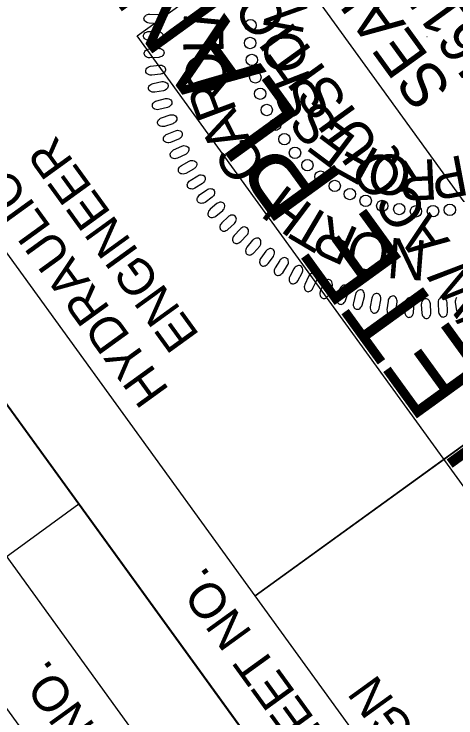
# Model space of a CAD drawing. Extents: x 474248 to 476123, y 501895 to 503900.
# Drawn here: x 474331.8 to 474393.9, y 503181.5 to 503280.5 of the extents above; entities that cross this region are included whole.
import ezdxf

# ---------------------------------------------------------------- set-up
doc = ezdxf.new("R2010")
doc.units = 0
for name, color, linetype in [('Sheet PE Seal Cell', 7, 'Continuous'), ('Sheet Plan CELL', 7, 'Continuous'), ('Sheet Sticker Incomplete CELL', 7, 'Continuous')]:
    doc.layers.add(name, color=color, linetype=linetype)

msp = doc.modelspace()

# ---------------------------------------------------------------- linework, layer by layer
at = {"layer": 'Sheet PE Seal Cell'}
msp.add_line((474389.783, 503277.324), (474389.821, 503277.351), dxfattribs=at)
for points in [[(474351.998, 503279.136), (474350.774, 503279.215), (474350.558, 503279.266), (474350.422, 503279.328), (474350.259, 503279.451), (474350.156, 503279.555), (474350.084, 503279.672), (474350.051, 503279.778), (474350.039, 503279.892), (474350.065, 503280.002), (474350.103, 503280.12), (474350.17, 503280.221), (474350.276, 503280.318), (474350.359, 503280.373), (474350.513, 503280.43), (474350.696, 503280.479), (474350.857, 503280.491), (474352.111, 503280.417), (474352.279, 503280.383), (474352.416, 503280.329), (474352.569, 503280.23), (474352.701, 503280.109), (474352.775, 503280.007), (474352.824, 503279.846), (474352.834, 503279.695), (474352.785, 503279.549), (474352.728, 503279.448), (474352.62, 503279.328), (474352.444, 503279.22), (474352.259, 503279.164), (474352.128, 503279.142)], [(474351.962, 503276.771), (474350.736, 503276.773), (474350.516, 503276.811), (474350.376, 503276.863), (474350.207, 503276.976), (474350.098, 503277.073), (474350.018, 503277.185), (474349.978, 503277.291), (474349.958, 503277.403), (474349.978, 503277.514), (474350.009, 503277.634), (474350.069, 503277.738), (474350.169, 503277.843), (474350.249, 503277.903), (474350.398, 503277.97), (474350.578, 503278.029), (474350.738, 503278.051), (474351.994, 503278.056), (474352.164, 503278.033), (474352.304, 503277.988), (474352.463, 503277.898), (474352.603, 503277.786), (474352.682, 503277.688), (474352.741, 503277.531), (474352.761, 503277.382), (474352.721, 503277.232), (474352.671, 503277.128), (474352.571, 503277.001), (474352.401, 503276.882), (474352.221, 503276.815), (474352.091, 503276.785)], [(474352.103, 503274.404), (474350.879, 503274.33), (474350.658, 503274.353), (474350.516, 503274.397), (474350.339, 503274.499), (474350.223, 503274.589), (474350.137, 503274.696), (474350.091, 503274.798), (474350.065, 503274.909), (474350.077, 503275.022), (474350.101, 503275.143), (474350.153, 503275.251), (474350.247, 503275.362), (474350.323, 503275.426), (474350.468, 503275.503), (474350.644, 503275.573), (474350.801, 503275.605), (474352.055, 503275.689), (474352.226, 503275.677), (474352.368, 503275.641), (474352.533, 503275.561), (474352.679, 503275.458), (474352.765, 503275.366), (474352.834, 503275.212), (474352.863, 503275.064), (474352.832, 503274.913), (474352.788, 503274.805), (474352.697, 503274.672), (474352.535, 503274.543), (474352.36, 503274.465), (474352.232, 503274.427)], [(474352.35, 503272.042), (474351.133, 503271.891), (474350.911, 503271.901), (474350.766, 503271.935), (474350.584, 503272.026), (474350.463, 503272.109), (474350.37, 503272.21), (474350.317, 503272.309), (474350.284, 503272.418), (474350.29, 503272.532), (474350.305, 503272.654), (474350.351, 503272.765), (474350.437, 503272.881), (474350.509, 503272.951), (474350.649, 503273.036), (474350.82, 503273.117), (474350.975, 503273.16), (474352.222, 503273.322), (474352.393, 503273.32), (474352.537, 503273.293), (474352.706, 503273.224), (474352.859, 503273.13), (474352.95, 503273.043), (474353.029, 503272.895), (474353.067, 503272.749), (474353.046, 503272.595), (474353.009, 503272.485), (474352.926, 503272.347), (474352.772, 503272.207), (474352.603, 503272.119), (474352.477, 503272.073)], [(474352.774, 503269.726), (474351.568, 503269.499), (474351.346, 503269.495), (474351.199, 503269.52), (474351.011, 503269.599), (474350.886, 503269.674), (474350.787, 503269.77), (474350.728, 503269.865), (474350.687, 503269.972), (474350.687, 503270.085), (474350.693, 503270.209), (474350.733, 503270.323), (474350.812, 503270.444), (474350.879, 503270.517), (474351.014, 503270.611), (474351.179, 503270.703), (474351.331, 503270.755), (474352.565, 503270.995), (474352.735, 503271.005), (474352.881, 503270.986), (474353.055, 503270.928), (474353.213, 503270.844), (474353.309, 503270.763), (474353.397, 503270.62), (474353.444, 503270.476), (474353.433, 503270.323), (474353.403, 503270.211), (474353.329, 503270.067), (474353.184, 503269.918), (474353.02, 503269.818), (474352.899, 503269.766)], [(474353.332, 503267.363), (474352.143, 503267.06), (474351.921, 503267.043), (474351.773, 503267.058), (474351.581, 503267.126), (474351.45, 503267.193), (474351.345, 503267.282), (474351.281, 503267.373), (474351.234, 503267.477), (474351.226, 503267.59), (474351.225, 503267.714), (474351.258, 503267.83), (474351.328, 503267.956), (474351.391, 503268.034), (474351.519, 503268.136), (474351.678, 503268.238), (474351.827, 503268.299), (474353.043, 503268.617), (474353.213, 503268.636), (474353.36, 503268.628), (474353.536, 503268.58), (474353.699, 503268.506), (474353.801, 503268.432), (474353.897, 503268.294), (474353.953, 503268.154), (474353.951, 503267.999), (474353.929, 503267.885), (474353.864, 503267.738), (474353.729, 503267.58), (474353.572, 503267.47), (474353.453, 503267.41)], [(474354.075, 503265.083), (474352.908, 503264.706), (474352.687, 503264.674), (474352.539, 503264.681), (474352.343, 503264.736), (474352.209, 503264.795), (474352.098, 503264.876), (474352.028, 503264.964), (474351.975, 503265.065), (474351.959, 503265.177), (474351.951, 503265.301), (474351.976, 503265.419), (474352.039, 503265.548), (474352.096, 503265.63), (474352.218, 503265.74), (474352.37, 503265.852), (474352.515, 503265.923), (474353.709, 503266.315), (474353.877, 503266.347), (474354.024, 503266.346), (474354.203, 503266.31), (474354.371, 503266.246), (474354.476, 503266.178), (474354.582, 503266.047), (474354.646, 503265.91), (474354.654, 503265.756), (474354.639, 503265.642), (474354.583, 503265.49), (474354.459, 503265.324), (474354.308, 503265.205), (474354.194, 503265.137)], [(474354.891, 503262.895), (474353.75, 503262.446), (474353.532, 503262.401), (474353.382, 503262.398), (474353.183, 503262.44), (474353.046, 503262.49), (474352.931, 503262.565), (474352.855, 503262.648), (474352.795, 503262.745), (474352.773, 503262.857), (474352.757, 503262.979), (474352.774, 503263.098), (474352.829, 503263.232), (474352.881, 503263.317), (474352.996, 503263.435), (474353.141, 503263.556), (474353.281, 503263.636), (474354.448, 503264.103), (474354.614, 503264.143), (474354.76, 503264.153), (474354.941, 503264.128), (474355.113, 503264.075), (474355.222, 503264.014), (474355.335, 503263.89), (474355.409, 503263.758), (474355.426, 503263.604), (474355.418, 503263.489), (474355.372, 503263.334), (474355.258, 503263.16), (474355.115, 503263.032), (474355.006, 503262.957)], [(474355.859, 503260.75), (474354.748, 503260.23), (474354.533, 503260.171), (474354.385, 503260.159), (474354.184, 503260.189), (474354.044, 503260.23), (474353.924, 503260.298), (474353.843, 503260.376), (474353.777, 503260.469), (474353.748, 503260.579), (474353.724, 503260.7), (474353.734, 503260.82), (474353.78, 503260.957), (474353.827, 503261.045), (474353.934, 503261.17), (474354.071, 503261.3), (474354.206, 503261.388), (474355.341, 503261.928), (474355.504, 503261.979), (474355.65, 503261.997), (474355.832, 503261.984), (474356.006, 503261.941), (474356.12, 503261.887), (474356.24, 503261.771), (474356.322, 503261.644), (474356.349, 503261.491), (474356.348, 503261.376), (474356.312, 503261.218), (474356.209, 503261.038), (474356.075, 503260.901), (474355.97, 503260.819)], [(474356.999, 503258.687), (474355.923, 503258.099), (474355.712, 503258.026), (474355.565, 503258.005), (474355.362, 503258.022), (474355.219, 503258.055), (474355.095, 503258.115), (474355.01, 503258.187), (474354.939, 503258.276), (474354.903, 503258.384), (474354.872, 503258.503), (474354.874, 503258.624), (474354.911, 503258.763), (474354.952, 503258.854), (474355.051, 503258.986), (474355.18, 503259.124), (474355.309, 503259.22), (474356.408, 503259.83), (474356.568, 503259.891), (474356.711, 503259.919), (474356.894, 503259.917), (474357.071, 503259.885), (474357.187, 503259.839), (474357.315, 503259.73), (474357.405, 503259.608), (474357.441, 503259.458), (474357.448, 503259.342), (474357.422, 503259.182), (474357.33, 503258.996), (474357.205, 503258.851), (474357.105, 503258.763)], [(474358.242, 503256.671), (474357.205, 503256.016), (474357, 503255.93), (474356.854, 503255.9), (474356.65, 503255.904), (474356.506, 503255.928), (474356.378, 503255.98), (474356.289, 503256.047), (474356.212, 503256.131), (474356.17, 503256.237), (474356.131, 503256.354), (474356.125, 503256.474), (474356.153, 503256.616), (474356.189, 503256.709), (474356.28, 503256.846), (474356.4, 503256.992), (474356.522, 503257.097), (474357.581, 503257.774), (474357.736, 503257.846), (474357.878, 503257.882), (474358.061, 503257.891), (474358.239, 503257.871), (474358.358, 503257.832), (474358.493, 503257.731), (474358.59, 503257.615), (474358.636, 503257.468), (474358.649, 503257.352), (474358.633, 503257.192), (474358.553, 503257.001), (474358.438, 503256.848), (474358.344, 503256.753)], [(474359.605, 503254.745), (474358.611, 503254.026), (474358.411, 503253.927), (474358.266, 503253.888), (474358.064, 503253.879), (474357.918, 503253.894), (474357.788, 503253.938), (474357.694, 503253.999), (474357.612, 503254.078), (474357.563, 503254.181), (474357.517, 503254.295), (474357.504, 503254.415), (474357.523, 503254.558), (474357.553, 503254.654), (474357.635, 503254.796), (474357.745, 503254.95), (474357.861, 503255.062), (474358.875, 503255.804), (474359.025, 503255.885), (474359.165, 503255.931), (474359.346, 503255.951), (474359.526, 503255.943), (474359.647, 503255.91), (474359.788, 503255.818), (474359.891, 503255.709), (474359.947, 503255.565), (474359.968, 503255.451), (474359.962, 503255.289), (474359.894, 503255.093), (474359.788, 503254.933), (474359.7, 503254.833)], [(474360.266, 503253.847), (474359.319, 503253.066), (474359.173, 503252.898), (474359.099, 503252.769), (474359.039, 503252.574), (474359.016, 503252.43), (474359.026, 503252.292), (474359.062, 503252.187), (474359.118, 503252.087), (474359.205, 503252.014), (474359.303, 503251.94), (474359.416, 503251.897), (474359.56, 503251.88), (474359.659, 503251.885), (474359.818, 503251.928), (474359.994, 503251.996), (474360.131, 503252.08), (474361.106, 503252.873), (474361.223, 503252.998), (474361.302, 503253.122), (474361.368, 503253.292), (474361.404, 503253.468), (474361.405, 503253.593), (474361.351, 503253.753), (474361.271, 503253.881), (474361.145, 503253.971), (474361.04, 503254.02), (474360.882, 503254.054), (474360.676, 503254.039), (474360.494, 503253.976), (474360.375, 503253.918)], [(474361.86, 503251.99), (474360.964, 503251.152), (474360.829, 503250.975), (474360.763, 503250.842), (474360.716, 503250.644), (474360.702, 503250.498), (474360.72, 503250.362), (474360.763, 503250.258), (474360.825, 503250.162), (474360.916, 503250.094), (474361.019, 503250.027), (474361.134, 503249.992), (474361.279, 503249.983), (474361.378, 503249.994), (474361.533, 503250.047), (474361.705, 503250.126), (474361.837, 503250.219), (474362.759, 503251.072), (474362.868, 503251.204), (474362.94, 503251.332), (474362.995, 503251.506), (474363.02, 503251.684), (474363.012, 503251.809), (474362.949, 503251.965), (474362.861, 503252.088), (474362.73, 503252.17), (474362.622, 503252.212), (474362.462, 503252.237), (474362.257, 503252.208), (474362.08, 503252.135), (474361.965, 503252.068)], [(474363.554, 503250.277), (474362.713, 503249.385), (474362.59, 503249.2), (474362.531, 503249.062), (474362.497, 503248.862), (474362.492, 503248.716), (474362.519, 503248.581), (474362.568, 503248.48), (474362.636, 503248.388), (474362.731, 503248.326), (474362.839, 503248.266), (474362.956, 503248.237), (474363.101, 503248.238), (474363.199, 503248.255), (474363.35, 503248.318), (474363.517, 503248.407), (474363.643, 503248.508), (474364.51, 503249.417), (474364.61, 503249.556), (474364.674, 503249.688), (474364.718, 503249.866), (474364.732, 503250.045), (474364.716, 503250.169), (474364.643, 503250.321), (474364.547, 503250.437), (474364.411, 503250.511), (474364.301, 503250.547), (474364.14, 503250.561), (474363.937, 503250.52), (474363.765, 503250.435), (474363.654, 503250.361)], [(474365.289, 503248.687), (474364.505, 503247.744), (474364.393, 503247.551), (474364.344, 503247.41), (474364.322, 503247.208), (474364.327, 503247.062), (474364.362, 503246.929), (474364.417, 503246.83), (474364.491, 503246.744), (474364.589, 503246.687), (474364.701, 503246.634), (474364.819, 503246.613), (474364.964, 503246.623), (474365.061, 503246.646), (474365.208, 503246.718), (474365.369, 503246.818), (474365.488, 503246.926), (474366.297, 503247.888), (474366.388, 503248.033), (474366.442, 503248.169), (474366.475, 503248.349), (474366.478, 503248.528), (474366.454, 503248.651), (474366.372, 503248.799), (474366.27, 503248.909), (474366.129, 503248.974), (474366.017, 503249.003), (474365.855, 503249.007), (474365.655, 503248.953), (474365.488, 503248.858), (474365.383, 503248.777)], [(474367.16, 503247.161), (474366.437, 503246.17), (474366.337, 503245.971), (474366.298, 503245.827), (474366.288, 503245.624), (474366.302, 503245.478), (474366.345, 503245.348), (474366.406, 503245.253), (474366.485, 503245.171), (474366.588, 503245.121), (474366.702, 503245.075), (474366.821, 503245.062), (474366.965, 503245.08), (474367.06, 503245.11), (474367.203, 503245.191), (474367.357, 503245.301), (474367.47, 503245.416), (474368.216, 503246.427), (474368.298, 503246.577), (474368.344, 503246.716), (474368.365, 503246.898), (474368.357, 503247.077), (474368.326, 503247.199), (474368.234, 503247.34), (474368.125, 503247.444), (474367.981, 503247.5), (474367.866, 503247.521), (474367.705, 503247.516), (474367.509, 503247.449), (474367.349, 503247.344), (474367.248, 503247.257)], [(474369.112, 503245.857), (474368.452, 503244.822), (474368.366, 503244.617), (474368.334, 503244.472), (474368.338, 503244.268), (474368.361, 503244.123), (474368.413, 503243.996), (474368.48, 503243.906), (474368.564, 503243.829), (474368.669, 503243.786), (474368.786, 503243.746), (474368.906, 503243.741), (474369.048, 503243.768), (474369.141, 503243.804), (474369.279, 503243.894), (474369.425, 503244.013), (474369.53, 503244.135), (474370.212, 503245.191), (474370.284, 503245.346), (474370.321, 503245.488), (474370.332, 503245.671), (474370.312, 503245.848), (474370.273, 503245.968), (474370.173, 503246.103), (474370.057, 503246.2), (474369.91, 503246.246), (474369.795, 503246.261), (474369.634, 503246.245), (474369.442, 503246.167), (474369.289, 503246.051), (474369.194, 503245.958)], [(474371.109, 503244.689), (474370.516, 503243.615), (474370.443, 503243.405), (474370.421, 503243.257), (474370.436, 503243.055), (474370.469, 503242.912), (474370.529, 503242.788), (474370.601, 503242.702), (474370.689, 503242.63), (474370.797, 503242.594), (474370.916, 503242.562), (474371.036, 503242.564), (474371.177, 503242.6), (474371.267, 503242.641), (474371.399, 503242.74), (474371.538, 503242.868), (474371.635, 503242.997), (474372.248, 503244.093), (474372.311, 503244.253), (474372.339, 503244.397), (474372.338, 503244.579), (474372.307, 503244.756), (474372.261, 503244.872), (474372.152, 503245.001), (474372.031, 503245.091), (474371.881, 503245.128), (474371.765, 503245.135), (474371.606, 503245.109), (474371.419, 503245.019), (474371.274, 503244.894), (474371.184, 503244.795)], [(474373.152, 503243.596), (474372.627, 503242.487), (474372.567, 503242.272), (474372.555, 503242.125), (474372.583, 503241.923), (474372.624, 503241.782), (474372.691, 503241.662), (474372.769, 503241.582), (474372.862, 503241.515), (474372.971, 503241.485), (474373.093, 503241.461), (474373.213, 503241.471), (474373.35, 503241.516), (474373.439, 503241.563), (474373.563, 503241.669), (474373.694, 503241.806), (474373.783, 503241.941), (474374.327, 503243.074), (474374.379, 503243.236), (474374.398, 503243.381), (474374.385, 503243.564), (474374.344, 503243.738), (474374.29, 503243.852), (474374.174, 503243.973), (474374.047, 503244.055), (474373.895, 503244.083), (474373.779, 503244.083), (474373.621, 503244.047), (474373.441, 503243.944), (474373.303, 503243.811), (474373.221, 503243.707)], [(474375.26, 503242.632), (474374.806, 503241.492), (474374.76, 503241.274), (474374.756, 503241.125), (474374.797, 503240.926), (474374.847, 503240.788), (474374.922, 503240.673), (474375.004, 503240.597), (474375.101, 503240.537), (474375.213, 503240.514), (474375.335, 503240.498), (474375.454, 503240.514), (474375.588, 503240.568), (474375.674, 503240.62), (474375.792, 503240.734), (474375.913, 503240.879), (474375.994, 503241.019), (474376.465, 503242.184), (474376.507, 503242.35), (474376.517, 503242.496), (474376.493, 503242.677), (474376.44, 503242.848), (474376.38, 503242.959), (474376.256, 503243.072), (474376.124, 503243.146), (474375.971, 503243.165), (474375.855, 503243.157), (474375.7, 503243.112), (474375.526, 503242.998), (474375.397, 503242.856), (474375.322, 503242.747)], [(474377.53, 503241.806), (474377.149, 503240.64), (474377.116, 503240.419), (474377.122, 503240.271), (474377.176, 503240.074), (474377.235, 503239.94), (474377.316, 503239.829), (474377.404, 503239.759), (474377.504, 503239.705), (474377.617, 503239.689), (474377.739, 503239.68), (474377.857, 503239.705), (474377.988, 503239.767), (474378.07, 503239.824), (474378.18, 503239.946), (474378.293, 503240.097), (474378.364, 503240.242), (474378.762, 503241.434), (474378.793, 503241.602), (474378.794, 503241.749), (474378.759, 503241.928), (474378.695, 503242.096), (474378.628, 503242.202), (474378.497, 503242.308), (474378.361, 503242.373), (474378.207, 503242.382), (474378.092, 503242.367), (474377.94, 503242.312), (474377.773, 503242.188), (474377.654, 503242.038), (474377.585, 503241.924)], [(474379.758, 503241.097), (474379.451, 503239.909), (474379.432, 503239.688), (474379.447, 503239.539), (474379.514, 503239.347), (474379.58, 503239.217), (474379.669, 503239.111), (474379.76, 503239.047), (474379.864, 503238.999), (474379.978, 503238.99), (474380.101, 503238.99), (474380.217, 503239.02), (474380.343, 503239.091), (474380.421, 503239.153), (474380.524, 503239.282), (474380.627, 503239.44), (474380.689, 503239.59), (474381.011, 503240.803), (474381.031, 503240.974), (474381.023, 503241.12), (474380.976, 503241.296), (474380.902, 503241.46), (474380.828, 503241.562), (474380.691, 503241.659), (474380.551, 503241.715), (474380.397, 503241.714), (474380.283, 503241.693), (474380.135, 503241.628), (474379.977, 503241.493), (474379.867, 503241.337), (474379.805, 503241.218)], [(474382.053, 503240.551), (474381.821, 503239.347), (474381.816, 503239.124), (474381.841, 503238.977), (474381.919, 503238.789), (474381.993, 503238.664), (474382.088, 503238.564), (474382.184, 503238.505), (474382.29, 503238.464), (474382.404, 503238.462), (474382.527, 503238.469), (474382.641, 503238.508), (474382.763, 503238.586), (474382.837, 503238.653), (474382.931, 503238.787), (474383.024, 503238.952), (474383.076, 503239.104), (474383.321, 503240.337), (474383.332, 503240.508), (474383.313, 503240.653), (474383.256, 503240.827), (474383.172, 503240.986), (474383.092, 503241.083), (474382.949, 503241.171), (474382.806, 503241.219), (474382.652, 503241.207), (474382.539, 503241.179), (474382.396, 503241.105), (474382.246, 503240.962), (474382.146, 503240.797), (474382.092, 503240.676)], [(474384.331, 503240.149), (474384.175, 503238.932), (474384.185, 503238.709), (474384.219, 503238.564), (474384.308, 503238.382), (474384.39, 503238.261), (474384.492, 503238.167), (474384.59, 503238.115), (474384.699, 503238.08), (474384.812, 503238.086), (474384.935, 503238.101), (474385.046, 503238.146), (474385.163, 503238.232), (474385.233, 503238.303), (474385.319, 503238.443), (474385.401, 503238.614), (474385.444, 503238.769), (474385.611, 503240.015), (474385.61, 503240.185), (474385.583, 503240.33), (474385.514, 503240.5), (474385.421, 503240.652), (474385.335, 503240.744), (474385.187, 503240.823), (474385.041, 503240.862), (474384.888, 503240.841), (474384.778, 503240.805), (474384.639, 503240.722), (474384.498, 503240.569), (474384.409, 503240.4), (474384.363, 503240.275)], [(474386.725, 503239.89), (474386.645, 503238.666), (474386.669, 503238.444), (474386.712, 503238.302), (474386.813, 503238.125), (474386.902, 503238.009), (474387.009, 503237.923), (474387.111, 503237.876), (474387.222, 503237.849), (474387.335, 503237.861), (474387.456, 503237.884), (474387.564, 503237.936), (474387.675, 503238.029), (474387.74, 503238.105), (474387.817, 503238.25), (474387.889, 503238.425), (474387.921, 503238.583), (474388.01, 503239.836), (474387.999, 503240.007), (474387.963, 503240.149), (474387.884, 503240.314), (474387.781, 503240.46), (474387.688, 503240.546), (474387.536, 503240.616), (474387.389, 503240.646), (474387.237, 503240.616), (474387.129, 503240.573), (474386.995, 503240.482), (474386.865, 503240.321), (474386.786, 503240.146), (474386.749, 503240.018)], [(474388.998, 503239.653), (474389.063, 503238.428), (474389.112, 503238.211), (474389.171, 503238.074), (474389.292, 503237.911), (474389.395, 503237.806), (474389.511, 503237.733), (474389.617, 503237.699), (474389.731, 503237.685), (474389.842, 503237.71), (474389.96, 503237.747), (474390.061, 503237.812), (474390.16, 503237.917), (474390.216, 503238), (474390.275, 503238.153), (474390.325, 503238.336), (474390.339, 503238.496), (474390.28, 503239.751), (474390.249, 503239.919), (474390.197, 503240.056), (474390.098, 503240.211), (474389.979, 503240.344), (474389.877, 503240.418), (474389.718, 503240.47), (474389.568, 503240.482), (474389.421, 503240.434), (474389.319, 503240.379), (474389.197, 503240.273), (474389.087, 503240.097), (474389.029, 503239.914), (474389.006, 503239.783)], [(474391.348, 503239.855), (474391.423, 503238.631), (474391.474, 503238.415), (474391.534, 503238.278), (474391.656, 503238.115), (474391.76, 503238.012), (474391.877, 503237.939), (474391.984, 503237.906), (474392.097, 503237.893), (474392.208, 503237.92), (474392.325, 503237.957), (474392.426, 503238.023), (474392.524, 503238.129), (474392.58, 503238.212), (474392.638, 503238.366), (474392.686, 503238.548), (474392.699, 503238.709), (474392.63, 503239.964), (474392.597, 503240.131), (474392.544, 503240.268), (474392.445, 503240.422), (474392.324, 503240.554), (474392.223, 503240.628), (474392.062, 503240.678), (474391.912, 503240.689), (474391.765, 503240.64), (474391.664, 503240.584), (474391.542, 503240.477), (474391.434, 503240.301), (474391.377, 503240.117), (474391.355, 503239.986)]]:
    msp.add_lwpolyline(points, close=True, dxfattribs=at)
msp.add_lwpolyline([(474393.927, 503240.634), (474393.83, 503240.451), (474393.785, 503240.264), (474393.772, 503240.132), (474393.773, 503240.002), (474393.924, 503238.784)], dxfattribs=at)
for centre in [(474365.008, 503278.929), (474364.948, 503276.429), (474365.193, 503274.051), (474365.684, 503271.606), (474366.369, 503269.3), (474367.285, 503267.014), (474368.459, 503264.916), (474369.763, 503262.91), (474371.251, 503260.989), (474372.997, 503259.255), (474374.849, 503257.647), (474376.834, 503256.331), (474378.968, 503255.191), (474381.183, 503254.238), (474383.52, 503253.521), (474385.903, 503253.083), (474388.247, 503252.764), (474390.646, 503252.78), (474393.015, 503252.97)]:
    msp.add_circle(centre, 0.801, dxfattribs=at)
at = {"layer": 'Sheet Plan CELL'}
for p, q in [((474414.228, 503110.329), (474296.891, 503272.338)), ((474414.228, 503110.329), (474296.891, 503272.338)), ((474404.081, 503102.966), (474286.766, 503265.007)), ((474365.666, 503198.69), (474456.749, 503264.656)), ((474320.652, 503196.916), (474340.872, 503211.618))]:
    msp.add_line(p, q, dxfattribs=at)
for points in [[(474365.666, 503198.69), (474307.015, 503279.669), (474398.139, 503345.665), (474456.797, 503264.676)], [(474393.908, 503095.616), (474276.579, 503257.677), (474296.891, 503272.338), (474414.228, 503110.329)], [(474424.343, 503117.653), (474365.666, 503198.69), (474456.797, 503264.676), (474515.447, 503183.634)]]:
    msp.add_lwpolyline(points, close=True, dxfattribs=at)
at = {"layer": 'Sheet Sticker Incomplete CELL'}
msp.add_lwpolyline([(474454.332, 503172.147), (474435.298, 503158.364), (474349.086, 503277.429), (474368.12, 503291.211)], close=True, dxfattribs=at)

# ---------------------------------------------------------------- texts
at = {"layer": 'Sheet PE Seal Cell'}
for s, height, rotation, p in [('46155', 6.2363, 125.8852, (474401.372, 503272.887)), ('SEAL', 6.2363, 125.8852, (474393.451, 503270.051)), ('N', 5.669, 79.55409, (474372.246, 503277.365)), ('I', 5.669, 84.55538, (474361.156, 503278.26)), ('L', 5.669, 91.04473, (474361.234, 503274.992)), ('O', 5.669, 95.43368, (474372.907, 503272.522)), ('O', 5.669, 97.53409, (474361.959, 503269.674)), ('R', 5.669, 110.5128, (474363.162, 503266.896)), ('I', 5.669, 111.31328, (474373.65, 503271.203)), ('S', 5.669, 119.25307, (474375.367, 503267.754)), ('S', 5.669, 127.19287, (474377.713, 503264.686)), ('A', 5.669, 117.00216, (474364.986, 503263.023)), ('E', 5.669, 143.07246, (474380.113, 503263.008)), ('C', 5.669, 123.49152, (474367.5, 503259.195)), ('F', 5.669, 151.01226, (474383.348, 503261.164)), ('O', 5.669, 166.89186, (474388.058, 503260.01)), ('R', 5.669, 182.77145, (474391.126, 503260.115)), ('P', 5.669, 190.71125, (474394.838, 503260.72)), ('H', 5.669, 142.95959, (474374.013, 503253.411)), ('T', 5.669, 149.44894, (474377.019, 503251.662)), ('R', 5.669, 155.9383, (474380.463, 503250.179)), ('O', 5.669, 168.91701, (474384.954, 503249.14)), ('N', 5.669, 175.40637, (474389.958, 503248.631))]:
    msp.add_text(s, height=height, rotation=rotation, dxfattribs=at).set_placement(p)
at = {"layer": 'Sheet Plan CELL'}
for s, p in [('ENGINEER', (474357.935, 503235.347)), ('HYDRAULICS', (474353.693, 503227.63)), ('R/W SHEET NO.', (474388.241, 503161.885)), ('PROJECT REFERENCE NO.', (474387.956, 503118.714)), ('ROADWAY DESIGN', (474418.893, 503137.627))]:
    msp.add_text(s, height=5.0001, rotation=125.90742, dxfattribs=at).set_placement(p)
at = {"layer": 'Sheet Sticker Incomplete CELL'}
for s, height, p in [('INCOMPLETE PLANS', 11.52, (474439.607, 503172.534)), ('DO NOT USE FOR R/W ACQUISITION', 5.76, (474443.33, 503179.242))]:
    msp.add_text(s, height=height, rotation=125.90742, dxfattribs=at).set_placement(p)

doc.saveas('drawing.dxf')
